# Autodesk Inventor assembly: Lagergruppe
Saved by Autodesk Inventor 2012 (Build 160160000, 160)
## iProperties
Company: CAD-Verlag
Created: 2004-12
Part Number: Lagergruppe
Document SubType Name: Assembly
Designer: jukr
Manufacturer: Standard
Standards Organization: Custom
Author: Jürgen Kronas
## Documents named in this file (6)
- C:\DemoDaten2012\CAD Daten\Daten Vault 2012 Inventor\Kapitel 6\6.4\Rollenbahn\Rollenbahn 1400\Lagergruppe.iam
- C:\DemoDaten2012\CAD Daten\Daten Vault 2012 Inventor\Kapitel 6\6.4\Rollenbahn\Bibliotheken\local.AFNOR.12.490.8.ipt
- C:\DemoDaten2012\CAD Daten\Daten Vault 2012 Inventor\Kapitel 6\6.4\Rollenbahn\Bibliotheken\local.DIN.162.250.8.ipt
- C:\DemoDaten2012\CAD Daten\Daten Vault 2012 Inventor\Kapitel 6\6.4\Rollenbahn\Rollenbahn 1400\pase30.iam
- C:\DemoDaten2012\CAD Daten\Daten Vault 2012 Inventor\Kapitel 6\6.4\Rollenbahn\Bibliotheken\local.AFNOR.63.110.8.ipt
- C:\DemoDaten2012\CAD Daten\Daten Vault 2012 Inventor\Kapitel 6\6.4\Rollenbahn\Bibliotheken\local.DIN.177.30.8.ipt
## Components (9 placed, 5 different names)
1. NF EN 24014  (Regelgewinde) M12 x 50:1
2. NF EN 24014  (Regelgewinde) M12 x 50:2
3. DIN 125-1  B B 13:1
4. DIN 125-1  B B 13:2
5. pase30:1 [sub-assembly]
6. NF EN 24032  (Regelgewinde) M12:1
7. DIN 434 14:1
8. NF EN 24032  (Regelgewinde) M12:2
9. DIN 434 14:2
